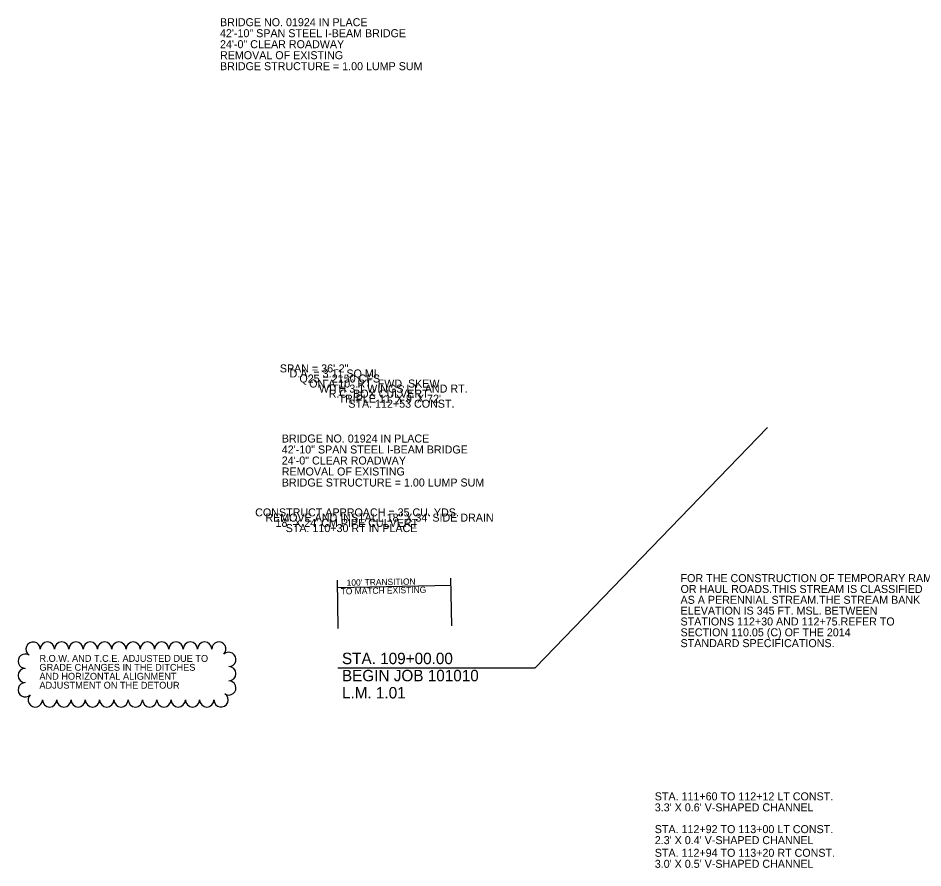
# Model space of a CAD drawing. Extents: x 9709 to 12772, y 9986 to 11806.
# Drawn here: x 10064 to 10855, y 11062 to 11806 of the extents above; entities that cross this region are included whole.
import ezdxf

# ---------------------------------------------------------------- set-up
doc = ezdxf.new("R2010")
doc.units = 0
for name, color, linetype in [('_30% NOTES', 7, 'Continuous'), ('JOB Text', 7, 'Continuous'), ('NOTES', 7, 'Continuous'), ('R_Culvert Annot', 7, 'Continuous'), ('RC Box Annot', 7, 'Continuous'), ('TEXT', 7, 'Continuous'), ('Transition Dimensions', 7, 'Continuous')]:
    doc.layers.add(name, color=color, linetype=linetype)

msp = doc.modelspace()

# ---------------------------------------------------------------- linework, layer by layer
at = {"layer": '_30% NOTES'}
for centre, start, end in [((10077.22, 11253.95), 0, 236.96364), ((10089.72, 11253.95), 0, 180), ((10102.22, 11253.95), 0, 180), ((10114.72, 11253.95), 0, 180), ((10127.22, 11253.95), 0, 180), ((10139.72, 11253.95), 0, 180), ((10152.22, 11253.95), 0, 180), ((10164.72, 11253.95), 0, 180), ((10177.22, 11253.95), 0, 180), ((10189.72, 11253.95), 0, 180), ((10202.22, 11253.95), 0, 180), ((10214.72, 11253.95), 0, 180), ((10227.22, 11253.95), 0, 180), ((10239.72, 11253.95), 314.11832, 180), ((10070.34, 11243.36), 56.96364, 270), ((10248.42, 11244.97), 270, 134.11832), ((10248.42, 11232.47), 270, 90), ((10070.34, 11230.86), 90, 270), ((10070.34, 11218.36), 90, 314.83174), ((10248.42, 11219.97), 237.04959, 90), ((10241.64, 11209.51), 180, 57.04959), ((10079.14, 11209.51), 134.83174, 0), ((10091.64, 11209.51), 180, 0), ((10104.14, 11209.51), 180, 0), ((10116.64, 11209.51), 180, 0), ((10129.14, 11209.51), 180, 0), ((10141.64, 11209.51), 180, 0), ((10154.14, 11209.51), 180, 0), ((10166.64, 11209.51), 180, 0), ((10179.14, 11209.51), 180, 0), ((10191.64, 11209.51), 180, 0), ((10204.14, 11209.51), 180, 0), ((10216.64, 11209.51), 180, 0), ((10229.14, 11209.51), 180, 0)]:
    msp.add_arc(centre, 6.25, start, end, dxfattribs=at)
at = {"layer": 'JOB Text'}
msp.add_lwpolyline([(10343.68, 11237.64), (10516.32, 11237.64), (10719.49, 11447.84)], dxfattribs=at)
at = {"layer": 'Transition Dimensions'}
for p, q in [((10344.15, 11271.94), (10343.33, 11314.15)), ((10343.45, 11307.8), (10442.77, 11309.84)), ((10443.58, 11274.21), (10442.63, 11315.98))]:
    msp.add_line(p, q, dxfattribs=at)

# ---------------------------------------------------------------- texts
at = {"layer": '_30% NOTES'}
for s, p in [('R.O.W. AND T.C.E. ADJUSTED DUE TO ', (10082.75, 11242.8)), ('GRADE CHANGES IN THE DITCHES', (10082.75, 11234.99)), ('AND HORIZONTAL ALIGNMENT ', (10082.75, 11227.18)), ('ADJUSTMENT ON THE DETOUR', (10082.75, 11219.36))]:
    msp.add_text(s, height=6, dxfattribs=at).set_placement(p)
at = {"layer": 'JOB Text'}
for s, p in [('STA. 109+00.00', (10347.34, 11240.78)), ('BEGIN JOB 101010', (10347.34, 11225.78)), ('L.M. 1.01', (10347.34, 11210.78))]:
    msp.add_text(s, height=10, dxfattribs=at).set_placement(p)
at = {"layer": 'NOTES'}
for s, p in [('BRIDGE NO. 01924 IN PLACE', (10240.68, 11798.99)), ('42\'-10" SPAN STEEL I-BEAM BRIDGE', (10240.68, 11789.36)), ('24\'-0" CLEAR ROADWAY', (10240.68, 11779.74)), ('REMOVAL OF EXISTING ', (10240.68, 11770.11)), ('BRIDGE STRUCTURE = 1.00 LUMP SUM', (10240.68, 11760.49)), ('BRIDGE NO. 01924 IN PLACE', (10294.71, 11434.72)), ('42\'-10" SPAN STEEL I-BEAM BRIDGE', (10294.71, 11425.1)), ('24\'-0" CLEAR ROADWAY', (10294.71, 11415.47)), ('REMOVAL OF EXISTING ', (10294.71, 11405.85)), ('BRIDGE STRUCTURE = 1.00 LUMP SUM', (10294.71, 11396.22)), ('STA. 111+60 TO 112+12 LT CONST.', (10620.97, 11121.58)), ("3.3' X 0.6' V-SHAPED CHANNEL ", (10620.97, 11111.95)), ('STA. 112+92 TO 113+00 LT CONST.', (10620.97, 11092.91)), ("2.3' X 0.4' V-SHAPED CHANNEL ", (10620.97, 11083.29)), ('STA. 112+94 TO 113+20 RT CONST.', (10620.97, 11072.21)), ("3.0' X 0.5' V-SHAPED CHANNEL ", (10620.97, 11062.58))]:
    msp.add_text(s, height=7, dxfattribs=at).set_placement(p)
at = {"layer": 'R_Culvert Annot'}
for s, p in [('CONSTRUCT APPROACH = 35 CU. YDS.', (10271.46, 11370.08)), ('REMOVE AND INSTALL 18" X 34\' SIDE DRAIN', (10280.35, 11365.5)), ('18" X 24\' CM PIPE CULVERT', (10289.24, 11360.91)), ('STA. 110+30 RT IN PLACE', (10298.12, 11356.33))]:
    msp.add_text(s, height=7, dxfattribs=at).set_placement(p)
at = {"layer": 'RC Box Annot'}
for s, p in [('SPAN = 36\'-2"', (10293.03, 11496.05)), ('D.A. = 3.11 SQ MI.', (10301.58, 11491.63)), ('Q25 = 2150 CFS', (10310.14, 11487.22)), ('ON A 10%%D RT. FWD. SKEW', (10318.69, 11482.81)), ('WITH 3:1 WINGS LT. AND RT.', (10327.25, 11478.39)), ('R.C. BOX CULVERT', (10335.8, 11473.98)), ("TRIPLE 11' X 9' X 72'", (10344.35, 11469.57)), ('STA. 112+53 CONST.', (10352.91, 11465.15))]:
    msp.add_text(s, height=7, dxfattribs=at).set_placement(p)
at = {"layer": 'TEXT'}
for s, p in [('FOR THE CONSTRUCTION OF TEMPORARY RAMPS', (10643.51, 11312.54)), ('OR HAUL ROADS.THIS STREAM IS CLASSIFIED', (10643.51, 11303.06)), ('AS A PERENNIAL STREAM.THE STREAM BANK', (10643.51, 11293.58)), ('ELEVATION IS 345 FT. MSL. BETWEEN', (10643.51, 11284.1)), ('STATIONS 112+30 AND 112+75.REFER TO', (10643.51, 11274.61)), ('SECTION 110.05 (C) OF THE 2014', (10643.51, 11265.13)), ('STANDARD SPECIFICATIONS.', (10643.51, 11255.65))]:
    msp.add_text(s, height=7, dxfattribs=at).set_placement(p)
at = {"layer": 'Transition Dimensions'}
for s, p in [("100' TRANSITION", (10351.53, 11309.31)), ('TO MATCH EXISTING', (10346.3, 11301.76))]:
    msp.add_text(s, height=5.5, rotation=1.06838, dxfattribs=at).set_placement(p)

doc.saveas('drawing.dxf')
